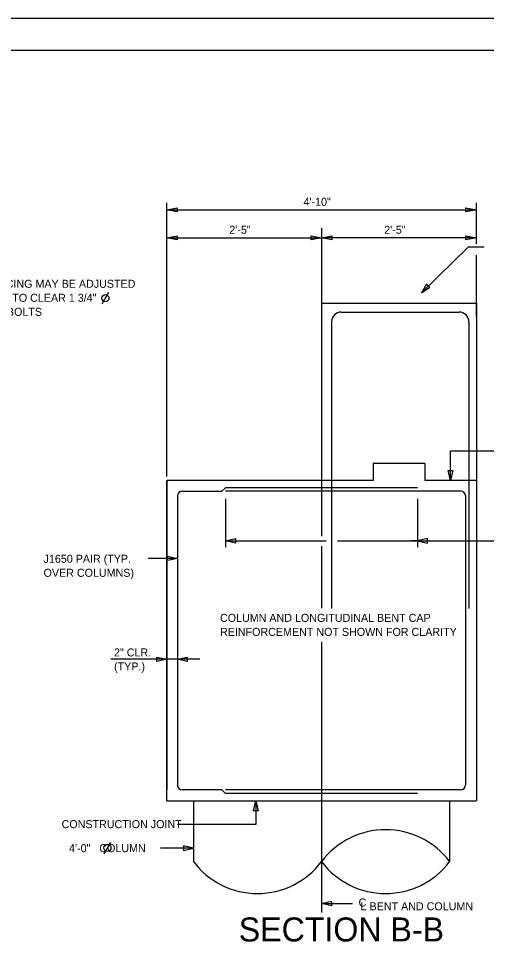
# Model space of a CAD drawing. Extents: x 1970675.2 to 1970711.3, y 796145.2 to 796167.2.
# Drawn here: x 1970689.34 to 1970696.64, y 796152.81 to 796167.25 of the extents above; entities that cross this region are included whole.
import ezdxf

# ---------------------------------------------------------------- set-up
doc = ezdxf.new("R2010")
doc.units = 0
for name, color, linetype in [('BR_AUTO DIMENSION', 7, 'Continuous'), ('BR_BORDER LINES', 7, 'Continuous'), ('BR_CENTER LINES', 7, 'Continuous'), ('BR_CONCRETE', 7, 'Continuous'), ('BR_REBAR', 7, 'Continuous'), ('BR_TEXT', 7, 'Continuous'), ('Level 31', 7, 'Continuous')]:
    doc.layers.add(name, color=color, linetype=linetype)

msp = doc.modelspace()

# ---------------------------------------------------------------- linework, layer by layer
at = {"layer": 'BR_AUTO DIMENSION'}
for p, q in [((1970691.651, 796160.092), (1970691.651, 796164.366)), ((1970696.485, 796163.726), (1970696.485, 796164.367)), ((1970691.651, 796164.259), (1970696.485, 796164.259)), ((1970691.651, 796163.822), (1970694.068, 796163.822)), ((1970696.485, 796163.822), (1970694.068, 796163.822)), ((1970696.485, 796162.592), (1970696.485, 796163.549)), ((1970692.568, 796159.742), (1970692.568, 796158.989)), ((1970695.568, 796159.742), (1970695.568, 796158.989)), ((1970692.568, 796159.086), (1970694.139, 796159.086)), ((1970694.315, 796159.086), (1970696.779, 796159.086)), ((1970691.818, 796158.814), (1970691.364, 796158.814)), ((1970692.169, 796157.237), (1970690.777, 796157.237)), ((1970693.041, 796155.029), (1970693.041, 796154.657)), ((1970693.041, 796154.657), (1970691.817, 796154.657)), ((1970692.068, 796154.288), (1970691.556, 796154.288)), ((1970694.068, 796153.422), (1970694.551, 796153.422))]:
    msp.add_line(p, q, dxfattribs=at)
for points in [[(1970691.814, 796164.227), (1970691.651, 796164.259), (1970691.814, 796164.29)], [(1970696.322, 796164.29), (1970696.485, 796164.259), (1970696.322, 796164.228)], [(1970691.814, 796163.791), (1970691.651, 796163.822), (1970691.814, 796163.853)], [(1970693.905, 796163.853), (1970694.068, 796163.822), (1970693.905, 796163.791)], [(1970694.23, 796163.791), (1970694.068, 796163.822), (1970694.23, 796163.853)], [(1970696.322, 796163.853), (1970696.485, 796163.822), (1970696.322, 796163.791)], [(1970695.709, 796163.099), (1970695.627, 796162.962), (1970695.761, 796163.05)], [(1970696.118, 796160.185), (1970696.082, 796160.029), (1970696.046, 796160.185)], [(1970692.724, 796159.05), (1970692.568, 796159.086), (1970692.724, 796159.122)], [(1970695.724, 796159.122), (1970695.568, 796159.086), (1970695.724, 796159.05)], [(1970691.662, 796158.85), (1970691.818, 796158.814), (1970691.662, 796158.778)], [(1970691.495, 796157.273), (1970691.651, 796157.237), (1970691.495, 796157.201)], [(1970691.973, 796157.201), (1970691.817, 796157.237), (1970691.973, 796157.273)], [(1970693.005, 796154.873), (1970693.041, 796155.029), (1970693.077, 796154.873)], [(1970691.912, 796154.252), (1970692.068, 796154.288), (1970691.912, 796154.324)], [(1970694.224, 796153.386), (1970694.068, 796153.422), (1970694.224, 796153.458)]]:
    msp.add_lwpolyline(points, close=True, dxfattribs=at)
for points in [[(1970695.627, 796162.962), (1970696.361, 796163.678), (1970696.606, 796163.678)], [(1970696.082, 796160.029), (1970696.082, 796160.492), (1970696.903, 796160.492)]]:
    msp.add_lwpolyline(points, dxfattribs=at)
at = {"layer": 'BR_BORDER LINES'}
msp.add_line((1970710.736, 796166.746), (1970677.07, 796166.746), dxfattribs=at)
at = {"layer": 'BR_CENTER LINES'}
for p, q in [((1970694.068, 796163.97), (1970694.068, 796162.529)), ((1970694.068, 796161.47), (1970694.068, 796159.162)), ((1970694.068, 796159.005), (1970694.068, 796158.036)), ((1970694.068, 796157.508), (1970694.068, 796153.282))]:
    msp.add_line(p, q, dxfattribs=at)
at = {"layer": 'BR_CONCRETE'}
for p, q in [((1970694.068, 796162.8), (1970694.068, 796160.029)), ((1970694.068, 796162.8), (1970696.485, 796162.8)), ((1970696.485, 796162.8), (1970696.485, 796160.029)), ((1970694.873, 796160.298), (1970694.873, 796160.029)), ((1970695.679, 796160.298), (1970694.873, 796160.298)), ((1970695.679, 796160.298), (1970695.679, 796160.029)), ((1970691.651, 796160.029), (1970691.651, 796155.196)), ((1970691.651, 796155.029), (1970691.651, 796160.029)), ((1970694.068, 796160.029), (1970691.651, 796160.029)), ((1970694.873, 796160.029), (1970694.068, 796160.029)), ((1970696.485, 796160.029), (1970695.679, 796160.029)), ((1970696.485, 796160.029), (1970696.485, 796155.029)), ((1970691.65, 796155.029), (1970692.068, 796155.029)), ((1970692.068, 796155.029), (1970696.068, 796155.029)), ((1970692.068, 796155.029), (1970692.068, 796154.078)), ((1970696.068, 796155.029), (1970696.484, 796155.029)), ((1970696.068, 796155.029), (1970696.068, 796154.078))]:
    msp.add_line(p, q, dxfattribs=at)
for centre, start, end in [((1970695.068, 796153.324), 37.0023, 142.9977), ((1970693.068, 796154.831), 217.0023, 322.9977), ((1970695.068, 796154.831), 217.0023, 322.9977)]:
    msp.add_arc(centre, 1.252, start, end, dxfattribs=at)
at = {"layer": 'BR_REBAR'}
for p, q in [((1970694.377, 796162.661), (1970696.215, 796162.661)), ((1970694.223, 796162.508), (1970694.223, 796158.029)), ((1970696.369, 796162.508), (1970696.369, 796158.029)), ((1970691.896, 796159.863), (1970692.513, 796159.863)), ((1970692.512, 796159.863), (1970692.568, 796159.918)), ((1970695.568, 796159.918), (1970692.568, 796159.918)), ((1970696.239, 796159.862), (1970692.568, 796159.863)), ((1970691.818, 796159.785), (1970691.817, 796155.275)), ((1970696.318, 796159.784), (1970696.318, 796155.524)), ((1970696.317, 796159.534), (1970696.317, 796155.274)), ((1970692.512, 796155.196), (1970691.895, 796155.197)), ((1970692.512, 796155.196), (1970692.567, 796155.141)), ((1970696.239, 796155.196), (1970692.567, 796155.196)), ((1970695.567, 796155.141), (1970692.567, 796155.141))]:
    msp.add_line(p, q, dxfattribs=at)
for centre, radius, start, end in [((1970694.379, 796162.505), 0.156, 91.025, 178.975), ((1970696.213, 796162.505), 0.156, 1.025, 88.975), ((1970691.896, 796159.785), 0.0781, 90, 180), ((1970696.24, 796159.784), 0.0781, 360, 90), ((1970691.895, 796155.275), 0.0781, 180, 270), ((1970696.239, 796155.274), 0.0781, 270, 360)]:
    msp.add_arc(centre, radius, start, end, dxfattribs=at)
at = {"layer": 'BR_TEXT'}
for p, q in [((1970690.642, 796162.787), (1970690.747, 796162.969)), ((1970692.568, 796159.086), (1970692.645, 796159.086)), ((1970695.568, 796159.086), (1970695.471, 796159.086)), ((1970690.674, 796154.201), (1970690.779, 796154.382))]:
    msp.add_line(p, q, dxfattribs=at)
for centre in [(1970690.695, 796162.878), (1970690.726, 796154.292)]:
    msp.add_circle(centre, 0.055, dxfattribs=at)
at = {"layer": 'Level 31'}
msp.add_lwpolyline([(1970675.236, 796145.246), (1970711.236, 796145.246), (1970711.236, 796167.246), (1970675.236, 796167.246)], close=True, dxfattribs=at)

# ---------------------------------------------------------------- texts
at = {"layer": 'BR_AUTO DIMENSION'}
for s, p in [('4\'-10"', (1970693.787, 796164.321)), ('2\'-5"', (1970692.628, 796163.884)), ('2\'-5"', (1970695.047, 796163.884))]:
    msp.add_text(s, height=0.125, dxfattribs=at).set_placement(p)
at = {"layer": 'BR_TEXT'}
for s, p in [('REINFORCING MAY BE ADJUSTED', (1970688.386, 796163.04)), ('SLIGHTLY TO CLEAR 1 3/4"  ', (1970688.386, 796162.821)), ('ANCHOR BOLTS', (1970688.386, 796162.602)), ('J1650 PAIR (TYP.', (1970689.729, 796158.745)), ('OVER COLUMNS)', (1970689.729, 796158.526)), ('COLUMN AND LONGITUDINAL BENT CAP', (1970692.483, 796157.822)), ('REINFORCEMENT NOT SHOWN FOR CLARITY', (1970692.483, 796157.603)), ('2" CLR.', (1970690.829, 796157.282)), ('(TYP.)', (1970690.829, 796157.063)), ('CONSTRUCTION JOINT', (1970690.01, 796154.6)), ('4\'-0"   COLUMN', (1970690.127, 796154.225)), ('C', (1970694.646, 796153.377)), ('L BENT AND COLUMN', (1970694.678, 796153.317))]:
    msp.add_text(s, height=0.125, rotation=360, dxfattribs=at).set_placement(p)
msp.add_text('SECTION B-B', height=0.375, dxfattribs=at).set_placement((1970692.776, 796152.83))

doc.saveas('drawing.dxf')
